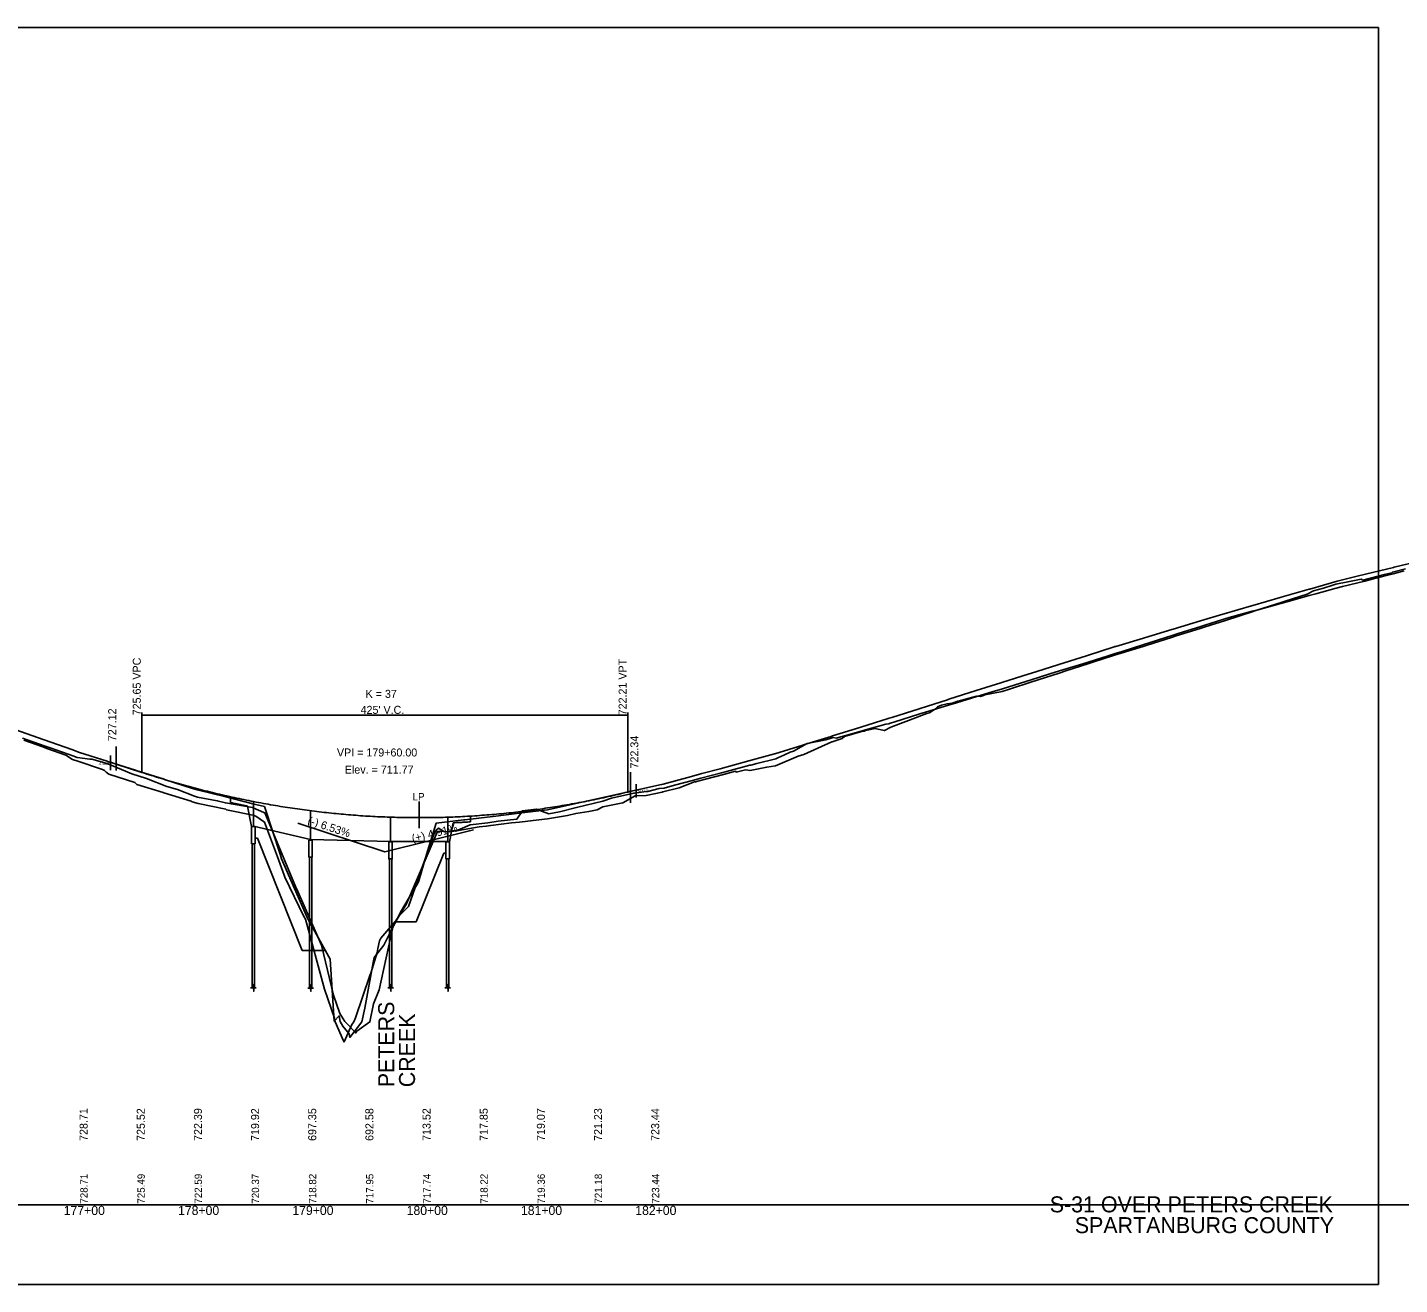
# Model space of a CAD drawing. Extents: x 1741783 to 1745041, y 1152835 to 1153935.
# Drawn here: x 1743200 to 1744400, y 1152835 to 1153935 of the extents above; entities that cross this region are included whole.
import ezdxf

# ---------------------------------------------------------------- set-up
doc = ezdxf.new("R2010")
doc.units = 0
for name, color, linetype in [('BR_CONCRETE', 7, 'Continuous'), ('BR_EXIST_GROUND_LT', 7, 'Continuous'), ('BR_EXIST_GROUND_RT', 7, 'Continuous'), ('BR_USER NOTES', 7, 'Continuous'), ('GN_Clip', 7, 'Continuous'), ('RD_DDB_GradeTX', 7, 'Continuous'), ('RD_DDB_Profile_EX', 7, 'Continuous'), ('RD_DDB_Profile_Lbl', 7, 'Continuous'), ('RD_DDB_Profile_PR', 7, 'Continuous'), ('RD_DDB_StaTX', 7, 'Continuous'), ('RD_DDB_StripGrade', 7, 'Continuous'), ('RD_DDB_VCLbl', 7, 'Continuous'), ('RD_GPK_Profile_Cell', 7, 'Continuous'), ('RD_SHT_TX', 7, 'Continuous')]:
    doc.layers.add(name, color=color, linetype=linetype)

msp = doc.modelspace()

# ---------------------------------------------------------------- linework, layer by layer
at = {"layer": 'BR_CONCRETE'}
for p, q in [((1743377.7, 1153257.2), (1743377.7, 1153262.3)), ((1743396.2, 1153236.2), (1743392.7, 1153254)), ((1743397.7, 1153236.6), (1743397.7, 1153258.1)), ((1743447.7, 1153224.9), (1743447.7, 1153250)), ((1743517.7, 1153223), (1743517.7, 1153244.3)), ((1743567.7, 1153223.2), (1743567.7, 1153244.4)), ((1743587.7, 1153240.3), (1743587.7, 1153245.3)), ((1743397.7, 1153236.6), (1743397.7, 1153236.2)), ((1743397.7, 1153236.6), (1743447.7, 1153224.9)), ((1743569.2, 1153222.8), (1743572.6, 1153239.5)), ((1743396.7, 1153095.1), (1743396.7, 1153221.2)), ((1743398.7, 1153095.1), (1743398.7, 1153221.2)), ((1743399.2, 1153226), (1743401.2, 1153226)), ((1743401.2, 1153226), (1743440.5, 1153127.8)), ((1743447.7, 1153224.9), (1743447.7, 1153224.4)), ((1743517.7, 1153223.2), (1743447.7, 1153224.9)), ((1743517.7, 1153223.2), (1743517.7, 1153222.8)), ((1743517.7, 1153223.2), (1743567.7, 1153223.2)), ((1743567.7, 1153223.2), (1743567.7, 1153222.8)), ((1743446.7, 1153094.9), (1743446.7, 1153209.4)), ((1743446.7, 1153209.4), (1743448.7, 1153209.4)), ((1743448.7, 1153094.9), (1743448.7, 1153209.4)), ((1743516.7, 1153095.1), (1743516.7, 1153207.8)), ((1743516.7, 1153207.8), (1743518.7, 1153207.8)), ((1743518.7, 1153095.1), (1743518.7, 1153207.8)), ((1743564.2, 1153212.8), (1743540.2, 1153152.8)), ((1743566.2, 1153212.8), (1743564.2, 1153212.8)), ((1743566.7, 1153095.1), (1743566.7, 1153207.8)), ((1743568.7, 1153095.1), (1743568.7, 1153207.8)), ((1743522.2, 1153152.8), (1743540.2, 1153152.8)), ((1743440.5, 1153127.8), (1743460.8, 1153127.8))]:
    msp.add_line(p, q, dxfattribs=at)
for points in [[(1743396.2, 1153236.2), (1743399.2, 1153236.2), (1743399.2, 1153221.2), (1743396.2, 1153221.2)], [(1743446.2, 1153224.4), (1743449.2, 1153224.4), (1743449.2, 1153209.4), (1743446.2, 1153209.4)], [(1743516.2, 1153222.8), (1743519.2, 1153222.8), (1743519.2, 1153207.8), (1743516.2, 1153207.8)], [(1743569.2, 1153222.8), (1743566.2, 1153222.8), (1743566.2, 1153207.8), (1743569.2, 1153207.8)]]:
    msp.add_lwpolyline(points, close=True, dxfattribs=at)
for points in [[(1743400.2, 1153095.1), (1743398, 1153095.1), (1743398, 1153092.1), (1743397.4, 1153098.1), (1743397.4, 1153095.1), (1743395.3, 1153095.1)], [(1743450.2, 1153094.9), (1743448, 1153094.9), (1743448, 1153091.9), (1743447.4, 1153097.9), (1743447.4, 1153094.9), (1743445.3, 1153094.9)], [(1743520.2, 1153095.1), (1743518, 1153095.1), (1743518, 1153092.1), (1743517.4, 1153098.1), (1743517.4, 1153095.1), (1743515.3, 1153095.1)], [(1743570.2, 1153095.1), (1743568, 1153095.1), (1743568, 1153092.1), (1743567.4, 1153098.1), (1743567.4, 1153095.1), (1743565.3, 1153095.1)]]:
    msp.add_lwpolyline(points, dxfattribs=at)
for points in [[(1743377.7, 1153257.2), (1743379.7, 1153256.7), (1743381.7, 1153256.3), (1743384.8, 1153255.6), (1743385.9, 1153255.4), (1743388.1, 1153254.9), (1743389.2, 1153254.7), (1743391.1, 1153254.3), (1743391.9, 1153254.2), (1743392.7, 1153254)], [(1743572.6, 1153239.5), (1743574.7, 1153239.6), (1743576.9, 1153239.7), (1743581.3, 1153239.9), (1743583.6, 1153240.1), (1743586.5, 1153240.2), (1743587.1, 1153240.3), (1743587.7, 1153240.3)]]:
    msp.add_open_spline(points, degree=3, dxfattribs=at)
at = {"layer": 'BR_EXIST_GROUND_LT'}
msp.add_lwpolyline([(1743195.6, 1153313.6), (1743215.6, 1153306.5), (1743220.9, 1153304.7), (1743240.5, 1153297.7), (1743241.2, 1153297.5), (1743243.5, 1153296.7), (1743254.7, 1153295.2), (1743256.5, 1153295.1), (1743269.7, 1153291.3), (1743291.4, 1153282.3), (1743297.8, 1153280.3), (1743304.2, 1153278.2), (1743322.1, 1153271.3), (1743331.2, 1153268.5), (1743346.2, 1153262.8), (1743348.7, 1153262), (1743366.1, 1153258.7), (1743373.2, 1153256.9), (1743397, 1153252.8), (1743397.5, 1153252.5), (1743406.8, 1153248.4), (1743407.7, 1153248.2), (1743435.3, 1153181.6), (1743435.5, 1153181.9), (1743436.5, 1153179.3), (1743457.2, 1153132.5), (1743467.8, 1153088.6), (1743473.2, 1153072.7), (1743477.8, 1153065.7), (1743479.4, 1153063.9), (1743486.9, 1153056.1), (1743487, 1153055.5), (1743488.2, 1153057), (1743499.7, 1153065.3), (1743502.7, 1153081), (1743507.7, 1153093.4), (1743520, 1153149.4), (1743523.3, 1153155), (1743525, 1153157.7), (1743533.3, 1153166.1), (1743555.7, 1153229.5), (1743556.7, 1153231.3), (1743557.6, 1153233.1), (1743559.7, 1153234.7), (1743565, 1153231.6), (1743576.6, 1153233), (1743587.5, 1153237.7), (1743602.7, 1153239.4), (1743611.8, 1153240.8), (1743628.2, 1153242.7), (1743633, 1153250), (1743645.2, 1153251.4), (1743656.1, 1153247.2), (1743665.5, 1153249.1), (1743679.1, 1153252.6), (1743680.5, 1153252.9), (1743688.7, 1153255), (1743703.5, 1153258.3), (1743711.1, 1153261.1), (1743730.5, 1153265.5), (1743731, 1153265.3), (1743739.2, 1153266.5), (1743742.7, 1153266.9), (1743752.8, 1153269.4), (1743757, 1153269.8), (1743766.2, 1153272.3), (1743782, 1153276.5), (1743789.1, 1153278.4), (1743807.1, 1153283.2), (1743811.5, 1153284.4), (1743832.1, 1153289.8), (1743833, 1153290), (1743838, 1153291.3), (1743854.9, 1153295.5), (1743856.6, 1153296.4), (1743861.7, 1153298.7), (1743867.4, 1153301.2), (1743870.2, 1153302.1), (1743881.6, 1153308.7), (1743882.1, 1153308.8), (1743898.5, 1153312.1), (1743903.2, 1153313.6), (1743904.9, 1153314.1), (1743907.5, 1153313.6), (1743927.4, 1153319.1), (1743931.2, 1153320.3), (1743951, 1153325.7), (1743953.5, 1153326.2), (1743954.8, 1153326.7), (1743955.8, 1153326.9), (1743957.9, 1153327.5), (1743980.8, 1153334.7), (1743985.7, 1153336.2), (1744005.7, 1153342.4), (1744012.7, 1153344.5), (1744030.7, 1153350), (1744043.9, 1153354.1), (1744053.1, 1153356.8), (1744068.8, 1153361.7), (1744078.1, 1153364.6), (1744094.6, 1153369.7), (1744103, 1153372.4), (1744120.5, 1153377.8), (1744128, 1153380.1), (1744145.6, 1153385.6), (1744151.7, 1153387.5), (1744157.8, 1153389.5), (1744176.6, 1153395.4), (1744182.3, 1153397.3), (1744201.6, 1153403.4), (1744206.7, 1153405.1), (1744226.5, 1153411.3), (1744230.1, 1153412.5), (1744246.6, 1153417.7), (1744251.3, 1153419), (1744271.5, 1153424.6), (1744276.6, 1153425.9), (1744296.5, 1153431.4), (1744301.9, 1153432.8), (1744321.4, 1153438.3), (1744327.3, 1153439.8), (1744345, 1153444.7), (1744350.6, 1153446.2), (1744369.9, 1153451), (1744377.7, 1153453), (1744394.9, 1153457.3), (1744404.3, 1153459.8)], dxfattribs=at)
at = {"layer": 'BR_EXIST_GROUND_RT'}
msp.add_lwpolyline([(1743196.9, 1153311.8), (1743213.5, 1153305.8), (1743216.9, 1153304.6), (1743233.6, 1153298.6), (1743239.5, 1153294.9), (1743244, 1153293.3), (1743265.8, 1153286), (1743267.6, 1153285.1), (1743269, 1153283.9), (1743271.2, 1153281.9), (1743293.9, 1153274.7), (1743295.7, 1153273.1), (1743318.9, 1153265.9), (1743319.5, 1153265.6), (1743343.2, 1153258.3), (1743344.3, 1153257.8), (1743349.3, 1153256.3), (1743373.5, 1153251.3), (1743374.2, 1153250.7), (1743398.7, 1153245.8), (1743399.1, 1153245.5), (1743399.9, 1153245.4), (1743407.3, 1153240), (1743418.8, 1153209.7), (1743424.7, 1153193.7), (1743425.3, 1153191.9), (1743441.9, 1153157.5), (1743443.2, 1153155.1), (1743459.9, 1153093.8), (1743468.8, 1153068.5), (1743469.3, 1153065.4), (1743476.5, 1153048.6), (1743477, 1153047.8), (1743483.8, 1153062.9), (1743485.5, 1153065.2), (1743487, 1153068.8), (1743499.6, 1153105.8), (1743500.4, 1153108), (1743505.9, 1153126), (1743506.6, 1153129.5), (1743508.1, 1153136.1), (1743509.3, 1153138.6), (1743523.6, 1153155.1), (1743531.7, 1153168.5), (1743558.5, 1153231.2), (1743559.2, 1153231.9), (1743560.5, 1153232.1), (1743569.1, 1153231.7), (1743577.1, 1153232.6), (1743595.3, 1153235.8), (1743601.4, 1153236.5), (1743605.3, 1153237.2), (1743623.5, 1153239.4), (1743630.5, 1153240.1), (1743647.5, 1153242.2), (1743655, 1153243), (1743672.5, 1153245.9), (1743679.9, 1153247.5), (1743691.3, 1153249.4), (1743698.4, 1153250.9), (1743703.4, 1153253.3), (1743720.9, 1153257), (1743731.6, 1153263), (1743741.2, 1153263.4), (1743755.4, 1153266.4), (1743755.8, 1153266.5), (1743770.1, 1153270.1), (1743783.5, 1153275.4), (1743784.9, 1153275.4), (1743786.6, 1153275.8), (1743801.2, 1153279.8), (1743809, 1153281.6), (1743819.5, 1153284.5), (1743820.2, 1153283.8), (1743828.3, 1153285.8), (1743832.2, 1153285.1), (1743846.8, 1153288.2), (1743854.5, 1153289.3), (1743874.3, 1153297.8), (1743879.3, 1153299.1), (1743903.8, 1153310.3), (1743904.1, 1153310.4), (1743912.7, 1153313.3), (1743914.9, 1153314.9), (1743928.9, 1153319.2), (1743932.1, 1153319.7), (1743933.1, 1153320.1), (1743937.5, 1153321.2), (1743941.3, 1153321.9), (1743949.7, 1153320.1), (1743955.3, 1153323.2), (1743979.4, 1153332.3), (1743980, 1153332.6), (1743986.8, 1153335), (1743989.1, 1153335.7), (1743993.7, 1153338.7), (1743996.1, 1153341), (1743999.6, 1153342.4), (1744004.5, 1153343.6), (1744009, 1153344.2), (1744014, 1153345.8), (1744014.4, 1153345.9), (1744030.3, 1153350.2), (1744033.7, 1153349.9), (1744036.4, 1153351), (1744037.6, 1153351.5), (1744052.7, 1153354.3), (1744060, 1153356.7), (1744077.7, 1153362.4), (1744084.3, 1153364.6), (1744102.7, 1153370.5), (1744108.5, 1153372.5), (1744127.7, 1153378.6), (1744132.2, 1153380.1), (1744151.1, 1153386.1), (1744153.9, 1153387), (1744176, 1153393.8), (1744179.6, 1153395), (1744200.9, 1153401.6), (1744205.1, 1153403), (1744225.9, 1153409.4), (1744230.4, 1153411), (1744248.2, 1153416.5), (1744272.3, 1153424.4), (1744272.9, 1153424.6), (1744275.4, 1153425.4), (1744297.7, 1153432.6), (1744300.3, 1153433.3), (1744319.5, 1153439.5), (1744325.2, 1153442.3), (1744333.9, 1153444.9), (1744341.1, 1153447.2), (1744344.7, 1153448.3), (1744355.2, 1153450.3), (1744366.7, 1153452.6), (1744368.4, 1153451.8), (1744387.3, 1153456.6), (1744391.1, 1153457.5), (1744393.7, 1153458.2), (1744394.2, 1153458.8), (1744405.7, 1153461.7)], dxfattribs=at)
at = {"layer": 'BR_USER NOTES'}
for p, q in [((1743277.7, 1153306.3), (1743277.7, 1153285.3)), ((1743272.7, 1153298.3), (1743272.7, 1153285.6)), ((1743272.7, 1153292.5), (1743277.7, 1153290.9)), ((1743727.7, 1153283.8), (1743727.7, 1153257)), ((1743727.7, 1153267), (1743732.7, 1153268.1)), ((1743732.7, 1153273.4), (1743732.7, 1153261.5)), ((1743542.7, 1153258), (1743542.7, 1153234.8)), ((1743542.7, 1153258), (1743542.7, 1153234.8)), ((1743447.7, 1153226.1), (1743447.7, 1153247.2))]:
    msp.add_line(p, q, dxfattribs=at)
at = {"layer": 'GN_Clip'}
for p, q in [((1742582, 1153935.4), (1744382, 1153935.4)), ((1744382, 1153935.4), (1744382, 1152835.4)), ((1744382, 1152835.4), (1742582, 1152835.4))]:
    msp.add_line(p, q, dxfattribs=at)
at = {"layer": 'RD_DDB_GradeTX'}
for p in [(1743436.7, 1153239), (1743590.4, 1153233.2)]:
    msp.add_line(p, (1743512.7, 1153214.2), dxfattribs=at)
at = {"layer": 'RD_DDB_Profile_EX'}
msp.add_lwpolyline([(1743189.8, 1153320.8), (1743213.8, 1153312.3), (1743214.7, 1153312), (1743238.8, 1153303.5), (1743239.7, 1153303.2), (1743244.7, 1153301.4), (1743245.6, 1153301.1), (1743269.7, 1153293.4), (1743270.4, 1153293.2), (1743294.6, 1153285.5), (1743295.2, 1153285.3), (1743319.6, 1153277.5), (1743319.9, 1153277.4), (1743344.5, 1153269.6), (1743348.6, 1153268.3), (1743373.5, 1153262.1), (1743398.5, 1153255.9), (1743407.4, 1153253.7), (1743408, 1153251.9), (1743421.2, 1153212), (1743422.4, 1153208), (1743445.1, 1153155.9), (1743445.5, 1153154.9), (1743447, 1153152.2), (1743465, 1153120.2), (1743468.3, 1153065.9), (1743472.7, 1153070.6), (1743473.5, 1153065.5), (1743475.9, 1153061.6), (1743481.4, 1153054.8), (1743482, 1153051.7), (1743492.6, 1153065.2), (1743495.3, 1153077.4), (1743502.5, 1153117.3), (1743503.4, 1153121.6), (1743511.7, 1153132.4), (1743515.5, 1153139.9), (1743527.2, 1153162.7), (1743533.1, 1153172.5), (1743541.7, 1153186.6), (1743542.4, 1153188.7), (1743549.3, 1153211.7), (1743557.6, 1153239), (1743581.9, 1153242), (1743582.6, 1153242.1), (1743607.1, 1153245.1), (1743607.6, 1153245.1), (1743632.6, 1153248.2), (1743654.9, 1153250.9), (1743679.9, 1153256.4), (1743704.9, 1153261.9), (1743729.8, 1153267.4), (1743754.8, 1153272.9), (1743756.3, 1153273.3), (1743781, 1153280), (1743790, 1153282.5), (1743806, 1153286.8), (1743831, 1153293.6), (1743853.6, 1153299.7), (1743853.9, 1153299.8), (1743878.3, 1153307.4), (1743878.9, 1153307.6), (1743903.2, 1153315.1), (1743904.2, 1153315.5), (1743928.3, 1153322.9), (1743929.2, 1153323.2), (1743953.1, 1153330.7), (1743953.8, 1153330.9), (1743955.1, 1153331.3), (1743956.2, 1153331.6), (1743980.1, 1153339.3), (1743981.1, 1153339.6), (1744005, 1153347.2), (1744006.1, 1153347.6), (1744030, 1153355.2), (1744051.5, 1153362), (1744052.4, 1153362.3), (1744076.4, 1153369.9), (1744077.4, 1153370.2), (1744101.4, 1153377.8), (1744102.3, 1153378.1), (1744126.4, 1153385.7), (1744127.3, 1153386), (1744150.7, 1153393.4), (1744151.4, 1153393.6), (1744152.1, 1153393.8), (1744176.3, 1153401.1), (1744177.2, 1153401.4), (1744201.3, 1153408.6), (1744202.3, 1153408.9), (1744226.2, 1153416.1), (1744245.8, 1153422), (1744246.9, 1153422.3), (1744270.9, 1153429.2), (1744271.9, 1153429.5), (1744296.1, 1153436.5), (1744296.8, 1153436.8), (1744321.3, 1153443.8), (1744321.8, 1153444), (1744345.7, 1153450.9), (1744363.3, 1153455.2), (1744370.5, 1153457), (1744395.2, 1153463), (1744395.7, 1153463.1), (1744420.1, 1153469)], dxfattribs=at)
at = {"layer": 'RD_DDB_Profile_PR'}
for p, q in [((1743277.7, 1153290.9), (1743300.2, 1153283.5)), ((1743725.2, 1153266.4), (1743727.7, 1153267))]:
    msp.add_line(p, q, dxfattribs=at)
msp.add_spline([(1743300.2, 1153283.5), (1743308.7, 1153280.8), (1743317.2, 1153278.2), (1743325.7, 1153275.6), (1743334.2, 1153273.2), (1743342.7, 1153270.9), (1743351.2, 1153268.6), (1743359.7, 1153266.5), (1743368.2, 1153264.4), (1743376.7, 1153262.5), (1743385.2, 1153260.6), (1743393.7, 1153258.9), (1743402.2, 1153257.2), (1743410.7, 1153255.7), (1743419.2, 1153254.2), (1743427.7, 1153252.9), (1743436.2, 1153251.6), (1743444.7, 1153250.4), (1743453.2, 1153249.3), (1743461.7, 1153248.4), (1743470.2, 1153247.5), (1743478.7, 1153246.7), (1743487.2, 1153246), (1743495.7, 1153245.4), (1743504.2, 1153244.9), (1743512.7, 1153244.6), (1743521.2, 1153244.3), (1743529.7, 1153244.1), (1743538.2, 1153244), (1743546.7, 1153244), (1743555.2, 1153244.1), (1743563.7, 1153244.2), (1743572.2, 1153244.5), (1743580.7, 1153244.9), (1743589.2, 1153245.4), (1743597.7, 1153246), (1743606.2, 1153246.7), (1743614.7, 1153247.4), (1743623.2, 1153248.3), (1743631.7, 1153249.3), (1743640.2, 1153250.3), (1743648.7, 1153251.5), (1743657.2, 1153252.8), (1743665.7, 1153254.1), (1743674.2, 1153255.6), (1743682.7, 1153257.1), (1743691.2, 1153258.8), (1743699.7, 1153260.5), (1743708.2, 1153262.4), (1743716.7, 1153264.3), (1743725.2, 1153266.4)], degree=3, dxfattribs=at)
at = {"layer": 'RD_DDB_VCLbl'}
for p, q in [((1743300.2, 1153336), (1743300.2, 1153283.5)), ((1743300.2, 1153333.5), (1743725.2, 1153333.5)), ((1743725.2, 1153336), (1743725.2, 1153266.4))]:
    msp.add_line(p, q, dxfattribs=at)
at = {"layer": 'RD_GPK_Profile_Cell'}
msp.add_line((1741866.9, 1152905.3), (1745041.2, 1152905.3), dxfattribs=at)

# ---------------------------------------------------------------- texts
at = {"layer": 'BR_USER NOTES'}
for s, height, p in [('-6.3800', 2, (1743262.2, 1153290.1)), ('LP', 6.4, (1743537, 1153259.1)), ('LP', 6.4, (1743537, 1153259.1)), ('+4.4120', 2, (1743733.5, 1153266.4))]:
    msp.add_text(s, height=height, dxfattribs=at).set_placement(p)
at = {"layer": 'RD_DDB_GradeTX'}
for s, rotation, p in [('(-) 6.53%', 341.9218, (1743444.6, 1153238.5)), ('(+) 4.91%', 13.7987, (1743537.2, 1153222.2))]:
    msp.add_text(s, height=7, rotation=rotation, dxfattribs=at).set_placement(p)
at = {"layer": 'RD_DDB_Profile_Lbl'}
for s, p in [('727.12', (1743277.7, 1153310.9)), ('722.34', (1743734.5, 1153287))]:
    msp.add_text(s, height=7, rotation=90, dxfattribs=at).set_placement(p)
for s, p in [('VPI = 179+60.00', (1743470.8, 1153297.5)), ('Elev. = 711.77', (1743477.7, 1153282.5))]:
    msp.add_text(s, height=7, dxfattribs=at).set_placement(p)
at = {"layer": 'RD_DDB_StaTX'}
for s, p in [('177+00', (1743231.8, 1152896.3)), ('178+00', (1743331.8, 1152896.3)), ('179+00', (1743431.8, 1152896.3)), ('180+00', (1743531.8, 1152896.3)), ('181+00', (1743631.8, 1152896.3)), ('182+00', (1743731.8, 1152896.3))]:
    msp.add_text(s, height=8, dxfattribs=at).set_placement(p)
at = {"layer": 'RD_DDB_StripGrade'}
for s, height, p in [('725.65 VPC', 7, (1743299.2, 1153333.5)), ('722.21 VPT', 7, (1743724.2, 1153333.5)), ('728.71', 7, (1743252.7, 1152961.1)), ('725.52', 7, (1743302.7, 1152961.1)), ('722.39', 7, (1743352.7, 1152961.1)), ('719.92', 7, (1743402.7, 1152961.1)), ('697.35', 7, (1743452.7, 1152961.1)), ('692.58', 7, (1743502.7, 1152961.1)), ('713.52', 7, (1743552.7, 1152961.1)), ('717.85', 7, (1743602.7, 1152961.1)), ('719.07', 7, (1743652.7, 1152961.1)), ('721.23', 7, (1743702.7, 1152961.1)), ('723.44', 7, (1743752.7, 1152961.1)), ('728.71', 6.4, (1743252.7, 1152906.2)), ('725.49', 6.4, (1743302.7, 1152906.2)), ('722.59', 6.4, (1743352.7, 1152906.2)), ('720.37', 6.4, (1743402.7, 1152906.2)), ('718.82', 6.4, (1743452.7, 1152906.2)), ('717.95', 6.4, (1743502.7, 1152906.2)), ('717.74', 6.4, (1743552.7, 1152906.2)), ('718.22', 6.4, (1743602.7, 1152906.2)), ('719.36', 6.4, (1743652.7, 1152906.2)), ('721.18', 6.4, (1743702.7, 1152906.2)), ('723.44', 6.4, (1743752.7, 1152906.2))]:
    msp.add_text(s, height=height, rotation=90, dxfattribs=at).set_placement(p)
at = {"layer": 'RD_DDB_VCLbl'}
for s, p in [('K = 37', (1743495.9, 1153348.8)), ("425' V.C.", (1743491.5, 1153334.8))]:
    msp.add_text(s, height=7, dxfattribs=at).set_placement(p)
at = {"layer": 'RD_SHT_TX'}
for s, rotation, p in [('PETERS ', 90, (1743520.9, 1153008.1)), ('CREEK', 90, (1743539.1, 1153008.1)), ('S-31 OVER PETERS CREEK', 360, (1744094.4, 1152898.6)), ('SPARTANBURG COUNTY', 360, (1744116.3, 1152880.4))]:
    msp.add_text(s, height=14, rotation=rotation, dxfattribs=at).set_placement(p)

doc.saveas('drawing.dxf')
